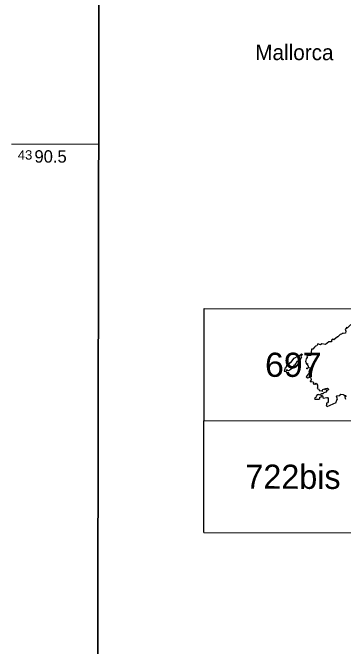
# Model space of a CAD drawing. Extents: x 483855 to 488461, y 4388206 to 4391419.
# Drawn here: x 487690 to 487957, y 4390095 to 4390606 of the extents above; entities that cross this region are included whole.
import ezdxf
from ezdxf.enums import TextEntityAlignment as Align

# ---------------------------------------------------------------- set-up
doc = ezdxf.new("R2010")
doc.units = 0
doc.header["$LTSCALE"] = 4
doc.linetypes.add('DOTTED', pattern=[1.5, 0.3, -1.2])
for name, color, linetype, lineweight in [('1', 7, 'Continuous', 13), ('2', 7, 'DOTTED', 13), ('3', 7, 'Continuous', 25)]:
    doc.layers.add(name, color=color, linetype=linetype, lineweight=lineweight)

msp = doc.modelspace()

# ---------------------------------------------------------------- linework, layer by layer
at = {"layer": '1'}
msp.add_line((487688.75, 4390500), (487759.12, 4390500), dxfattribs=at)
at = {"layer": '1', "lineweight": 25}
for p, q in [((487843.91, 4390186.56), (487844.26, 4390367.21)), ((487844.25, 4390367.21), (488398.49, 4390366.15)), ((487844.08, 4390276.88), (488398.31, 4390275.82)), ((487843.9, 4390186.56), (488398.14, 4390185.5))]:
    msp.add_line(p, q, dxfattribs=at)
at = {"layer": '1', "lineweight": 35}
msp.add_lwpolyline([(484045.03, 4391144.08), (487760.33, 4391137.02), (487755.66, 4388682.02), (484040.36, 4388689.09)], close=True, dxfattribs=at)
at = {"layer": '3'}
for points in [[(487964.58, 4390354.54), (487964.07, 4390354.83), (487962.24, 4390353.76), (487959.98, 4390351.69), (487958.89, 4390351.91), (487959.14, 4390351.12), (487957.96, 4390350.58), (487958.6, 4390349.15), (487958.25, 4390347.5), (487956.55, 4390347.15)], [(487956.55, 4390347.15), (487955.7, 4390347.24), (487955.1, 4390346.52), (487953.99, 4390346.26), (487952.19, 4390344.38), (487951.77, 4390344.41), (487949, 4390342.11), (487948.36, 4390342.67), (487946.92, 4390341.69), (487947.12, 4390340.49), (487944.8, 4390340.41), (487942.3, 4390338.34)], [(487942.3, 4390338.34), (487939.3, 4390338.85), (487938.07, 4390337.94), (487936.11, 4390338.84), (487935.18, 4390337.08), (487934.08, 4390337), (487933.2, 4390336.24), (487932.08, 4390334.4), (487930.79, 4390334.39), (487930.51, 4390332.17), (487930.78, 4390331.09), (487930.22, 4390330.08), (487930.35, 4390329.35), (487928.27, 4390329.5)], [(487913.1, 4390322.95), (487913.62, 4390323.71), (487914.18, 4390323.72), (487916.87, 4390327.28), (487919.85, 4390328.81), (487920.92, 4390329.01), (487922.94, 4390330.68), (487923.7, 4390330.25), (487922.64, 4390329.14), (487922.35, 4390328.05), (487922.85, 4390328.01), (487921.56, 4390325.35), (487920.9, 4390325.29), (487920.68, 4390324.71), (487919.72, 4390324.21), (487919.61, 4390324.81), (487919.23, 4390324.74), (487918.18, 4390322.9)], [(487928.27, 4390329.5), (487927.04, 4390328.58), (487927.41, 4390327.85), (487926.6, 4390326.66), (487926, 4390324.48), (487926.31, 4390324.32), (487926.51, 4390322.82)], [(487913.1, 4390322.95), (487910.7, 4390321.13), (487910.09, 4390319.38), (487909.31, 4390318.78), (487908.91, 4390316.82), (487909.99, 4390316.55), (487910.62, 4390316.84), (487910.65, 4390317.99), (487911.28, 4390317.36), (487913.06, 4390317.63)], [(487918.18, 4390322.9), (487917.26, 4390321.49), (487916.45, 4390321.28), (487916.82, 4390320.89), (487915.55, 4390319.88), (487915.19, 4390318.88), (487913.06, 4390317.63)], [(487926.51, 4390322.82), (487926.78, 4390322.53), (487927.66, 4390322.81), (487927.37, 4390321.76), (487927.89, 4390321.73), (487928.08, 4390320.06), (487929.57, 4390319.53), (487930.05, 4390318.72), (487929.17, 4390317.85), (487929.25, 4390317.02), (487929.53, 4390317.04), (487928.75, 4390316.36), (487928.92, 4390315.33), (487926.65, 4390312.24), (487928.01, 4390311.29), (487929.45, 4390311.97)], [(487929.45, 4390311.97), (487930.31, 4390311.36), (487930.64, 4390309.67), (487929.7, 4390308.72), (487929.8, 4390308.4), (487930.99, 4390308.54), (487931.94, 4390308.11), (487932.44, 4390307.68), (487932.37, 4390306.6), (487933.72, 4390306.4), (487933.75, 4390306.11), (487934.69, 4390306.99), (487935.74, 4390305.58), (487935.75, 4390303.66)], [(487942.32, 4390302.86), (487943.87, 4390302.97), (487944.83, 4390301.9), (487943.68, 4390301.12), (487943.08, 4390301.52), (487943.41, 4390300.95), (487942.42, 4390299.77), (487940.9, 4390299.25), (487939.94, 4390298.43), (487938.96, 4390298.36), (487937.09, 4390297.33), (487936.86, 4390297.92), (487936.24, 4390297.55), (487935.46, 4390297.65), (487934.56, 4390296.6), (487934.33, 4390295.55)], [(487935.75, 4390303.66), (487935.53, 4390302.73), (487936.73, 4390302.27), (487937.09, 4390301.23), (487938.58, 4390300.9), (487939.23, 4390301.28), (487940.08, 4390300.29), (487939.82, 4390300.95), (487940.13, 4390302.09), (487941.44, 4390302.5), (487942.12, 4390301.74), (487941.54, 4390302.51), (487941.87, 4390302.12), (487941.82, 4390302.58), (487942.18, 4390302.37), (487942.23, 4390302.73), (487942.37, 4390302.04), (487942.32, 4390302.86)], [(487934.33, 4390295.55), (487933.38, 4390294.99), (487933.69, 4390294.16), (487936.94, 4390294.14), (487937.57, 4390294.76), (487937.67, 4390295.71), (487938.91, 4390296.12), (487938.71, 4390297.04), (487939.22, 4390297.4), (487939.89, 4390296.73), (487940.38, 4390294.9), (487943.41, 4390295.52), (487943.89, 4390295.49), (487944.35, 4390294.71)], [(487951.6, 4390294.95), (487951.02, 4390296.51), (487951.27, 4390296.95), (487953.85, 4390297.19), (487954.48, 4390298.08), (487956.48, 4390297.93), (487957.02, 4390297.41), (487957.32, 4390297.57), (487957.39, 4390297.01), (487958.09, 4390297.32), (487958.12, 4390296.64), (487958.3, 4390297.18), (487958.66, 4390296.98), (487958.58, 4390296.36), (487957.88, 4390295.83), (487958.22, 4390294.17)], [(487944.35, 4390294.71), (487944.28, 4390292.06), (487943.78, 4390291.18), (487942.97, 4390290.99), (487942.9, 4390290.37), (487943.31, 4390290.17), (487942.77, 4390288.93), (487943.44, 4390288.31), (487950.69, 4390291.39), (487951.02, 4390292.94), (487951.48, 4390293.3), (487951.44, 4390293.84), (487951.79, 4390293.78), (487951.6, 4390294.95)]]:
    msp.add_lwpolyline(points, dxfattribs=at)
msp.add_lwpolyline([(487927.59, 4390319.17), (487927.67, 4390318.56), (487927.08, 4390318.59), (487927.1, 4390319.34)], close=True, dxfattribs=at)

# ---------------------------------------------------------------- texts
at = {"layer": '2'}
msp.add_text('Mallorca', height=12.5, rotation=359.891, dxfattribs=at).set_placement((487885.49, 4390567.79))
at = {"layer": '2', "width": 1.05}
msp.add_text('43', height=7.5, dxfattribs=at).set_placement((487693.74, 4390487.5))
at = {"layer": '2'}
msp.add_text('90.5', height=10, dxfattribs=at).set_placement((487707.19, 4390485))
at = {"layer": '2', "width": 1.05}
msp.add_text('697', height=19.5, rotation=359.891, dxfattribs=at).set_placement((487916.18, 4390312.14), align=Align.CENTER)
at = {"layer": '2'}
msp.add_text('722bis', height=19.5, rotation=359.891, dxfattribs=at).set_placement((487915.94, 4390221.81), align=Align.CENTER)

doc.saveas('drawing.dxf')
